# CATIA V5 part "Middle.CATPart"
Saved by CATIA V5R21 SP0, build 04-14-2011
Part number: Part1.6
Material "Fire Red": density 7860 kg/m3, Young's modulus 2e+11 Pa, Poisson ratio 0.266
Bounding box of the stored display mesh (mm): x 0 to 10, y -25.515 to 25.515, z 19.313 to 82.683
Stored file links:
  C:\Users\RIAD MAHAMUD PIASH\Desktop\Project\Middle.CATPart
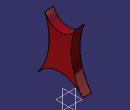
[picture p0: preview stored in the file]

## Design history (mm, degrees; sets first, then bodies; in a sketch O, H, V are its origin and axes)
Body1 (main body), material "Fire Red"
  Sketch1 on yz-plane, origin (0, 0, 0), H (0, 1, 0), V (0, 0, 1)
    arc A1 centre (0, 0) radius 32 from (25.515, 19.3128) to (-25.515, 19.3128) ccw
    arc A2 centre (0, 90.0295) radius 19 from (-17.5224, 82.6833) to (17.5224, 82.6833) ccw
    point P1 (0, 90.0295)
    arc A3 centre (76.5451, 57.9383) radius 64 from (17.5224, 82.6833) to (25.515, 19.3128) ccw
    point P3 (25.515, 19.3128)
    point P4 (17.5224, 82.6833)
    point P5 (-25.515, 19.3128)
    point P6 (-17.5224, 82.6833)
    arc A4 centre (-76.5451, 57.9383) radius 64 from (-17.5224, 82.6833) to (-25.515, 19.3128) cw
    radius A2 = 19
    radius A1 = 32
    radius A3 = 64
    coincidence: P1 V
    fix: A2, A1
    tangency: A3 A2, A3 A1
    symmetry: P3 P5 V, P4 P6 V, A3 A4 V
  Pad1: profile Sketch1, direction (1, 0, 0), length 10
